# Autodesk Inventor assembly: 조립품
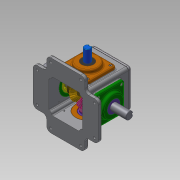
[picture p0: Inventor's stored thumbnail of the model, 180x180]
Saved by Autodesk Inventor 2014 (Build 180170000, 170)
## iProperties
Created: 2019-12
Part Number: 조립품
Document SubType Name: Assembly
Designer: net
Author: net
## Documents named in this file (16)
- C:\Users\net\Desktop\391204V1064\조립품.iam
- C:\Users\net\Desktop\391204V1064\본체.ipt
- C:\Users\net\Desktop\391204V1064\개스킷.ipt
- C:\Users\net\Desktop\391204V1064\메인베벨기어.ipt
- C:\Users\net\Desktop\391204V1064\메인축.ipt
- C:\Users\net\Desktop\391204V1064\메인커버.ipt
- C:\Users\net\Desktop\391204V1064\베어링 6203.ipt
- C:\Users\net\Desktop\391204V1064\베어링 6204.ipt
- C:\Users\net\Desktop\391204V1064\볼트 M4.ipt
- C:\Users\net\Desktop\391204V1064\상부커버.ipt
- C:\Users\net\Desktop\391204V1064\서브베벨기어.ipt
- C:\Users\net\Desktop\391204V1064\서브축.ipt
- C:\Users\net\Desktop\391204V1064\서브커버.ipt
- C:\Users\net\Desktop\391204V1064\오일 실 17 32 8.ipt
- C:\Users\net\Desktop\391204V1064\오일 실 20 35 8.ipt
- C:\Users\net\Desktop\391204V1064\키 4x4.ipt
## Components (1 placed, 1 different names)
1. 개스킷:1
